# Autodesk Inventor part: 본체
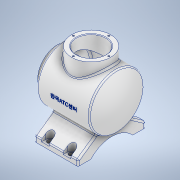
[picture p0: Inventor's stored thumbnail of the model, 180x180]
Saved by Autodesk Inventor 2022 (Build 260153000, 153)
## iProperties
Created: 2023-04
Part Number: 본체
Material: 알루미늄 6061
Document SubType Name: Modeling
Designer: Admin
Mass: 1296.7 g
Surface Area: 1060.45 cm^2
Volume: 480.258 cm^3
Density: 2.7 g/cm^3
Appearance: 알루미늄 - 평지
Author: Admin
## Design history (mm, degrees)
sketch "스케치1"
  geometry: L1 (-96.549, 0)-(166.291, 0) reference; L2 (0, -10.134)-(0, 60.805) reference; L3 (8.743, 0)-(128.743, 0); L4 (42.336, 50)-(-54, 50); L5 (-54, 50)-(-54, 43); L6 (-54, 0)-(54, 0); L7 (-54, 43)-(-54, 0); A1 r 113 centre (-59, 0) between (54, 0) and (42.336, 50); 3 further points
  constraints: 10 end point, 6 point on line, 2 perpendicular, 2 point on circle, 2 symmetric about line, 1 centre point, 1 collinear, 1 horizontal
  dimensions: "d2" = 113 radius of A1; "d4" = 108 distance from line of L6.end L5; "d75" = 100 diameter of L4 L1
revolve "회전1" sketch "스케치1" stored, may be unused: angle "d7" = 360 deg
sketch "스케치2"
  geometry: L1 (-77, -62)-(-77, 62); L2 (-134.515, 0)-(22.419, 0) reference; L3 (0, -110.456)-(0, 116.899) reference; L4 (-60, -77.977)-(-60, 84.42); L5 (-77, 62)-(-67, 62); L6 (-67, 62)-(-34.468, 15.54); L7 (-34.468, 15.54)-(-34.468, -15.54); L8 (-34.468, -15.54)-(-67, -62); L9 (-67, -62)-(-77, -62); A1 r 52.096 centre (-112.096, 0) between (-77, -38.5) and (-77, 38.5); 1 further point
  constraints: 14 end point, 4 symmetric about line, 2 point on circle, 2 point on line, 2 vertical, 1 centre point, 1 horizontal, 1 parallel, 1 perpendicular, 1 tangent
  dimensions: "d8" = 77 distance between parallel lines of L1 L3; "d9" = 124 distance of L1.start L1.end; "d11" = 77 distance of A1.end A1.start; "d12" = 17 distance between parallel lines of L1 L4; "d13" = 162.39677 distance of L4.start L4.end; "d14" = 55 deg angle of L6 L5; "d15" = 42.53177 distance between parallel lines of L1 L7; "d16" = 10 distance of L1.end L5.end
extrude "돌출1" join sketch "스케치2" distance "d17" = 34; taper "d18" = 0 deg; dims "d98" = 46, "d99" = 0
sketch "스케치12"
  geometry: L1 (38.5, -77)-(62, -77) reference; L2 (-86.8, 0)-(86.8, 0) reference; L3 (0, -102.4)-(0, 75.4) reference; C1 r 36 at (0, 0); 1 further point
  constraints: 1 centre point, 1 point on line
  dimensions: "d76" = 72 diameter of C1; "d77" = 77 distance from line of L1 C1.centre
extrude "돌출5" join sketch "스케치12" distance "d78" = 12; taper "d79" = 0 deg
node "작업 평면1"
sketch "스케치3"
  geometry: L1 (13, 23.5)-(13, 15.5); L2 (27, 23.5)-(27, 15.5); L3 (0, 23.5)-(80, 23.5) reference; L4 (0, 0)-(0, 23.5) reference; L5 (13, 23.5)-(27, 23.5); L6 (53, 23.5)-(53, 15.5); L7 (67, 23.5)-(67, 15.5); L8 (53, 23.5)-(67, 23.5); A1 r 7 centre (20, 15.5) between (13, 15.5) and (27, 15.5); A2 r 7 centre (60, 15.5) between (53, 15.5) and (67, 15.5); 1 further point
  constraints: 12 end point, 4 point on circle, 4 point on line, 4 tangent, 4 vertical, 2 centre point, 1 collinear, 1 perpendicular
  dimensions: "d20" = 14 distance between parallel lines of L2 L1; "d21" = 8 distance from line of L3 L1.end; "d22" = 20 distance from line of L4 A1.centre; "d23" = 14 distance between parallel lines of L7 L6; "d24" = 8 distance from line of L3 A2.centre; "d25" = 40 distance of A1.centre A2.centre
extrude "돌출2" cut sketch "스케치3" distance "d26" = 30; taper "d27" = 0 deg
node "작업 평면3"
sketch "스케치13"
  geometry: L1 (0, -102.4)-(0, 75.4) reference; L2 (-90, 0)-(78, 0) reference; L3 (-66, 36)-(-66, -36) reference; L4 (-66, 0)-(-47, 0); L5 (-47, 0)-(-47, 27); L6 (-47, 27)-(-66, 27); L7 (-66, 27)-(-66, 0); L8 (-47, 0)-(37.887, 0); L9 (37.887, 0)-(37.887, 43); L10 (37.887, 43)-(-47, 43); L11 (-47, 43)-(-47, 0); L12 (37.887, 0)-(47, 0); A1 r 113 centre (-59, 0) between (42.336, -50) and (42.336, 50) reference; A2 r 106 centre (-59, 0) between (47, 0) and (37.887, 43); 4 further points
  constraints: 18 end point, 4 parallel, 2 horizontal, 2 perpendicular, 2 point on circle, 1 centre point, 1 midpoint, 1 point on line
  dimensions: "d81" = 7 radial gap between concentric circles of A1 A2; "d82" = 54 diameter of L6 L2; "d83" = 86 diameter of L10 L2; "d84" = 19 distance of L5.end L6.end
revolve "회전3" sketch "스케치13" stored, may be unused: angle "d85" = 360 deg
sketch "스케치5"
  geometry: L1 (90, 0)-(-78, 0) reference; L2 (0, -86.8)-(0, 86.8) reference; L3 (66, -36)-(66, 36) reference; C1 r 36 at (4, 0); 1 further point
  constraints: 1 centre point, 1 point on line
  dimensions: "d35" = 72 diameter of C1; "d80" = 62 distance from line of L3 C1.centre
extrude "돌출3" join sketch "스케치5" stored distance "d37" = 30; taper "d38" = 0 deg
sketch "스케치6"
  geometry: C1 r 36 at (0, 0) reference; C2 r 27 at (0, 0); 1 further point
  constraints: 1 centre point, 1 coincident
  dimensions: "d39" = 54 diameter of C2
extrude "돌출4" cut sketch "스케치6" stored distance "d40" = 10; taper "d41" = 0 deg
sketch "스케치7"
  geometry: L1 (13, -23.5)-(13, -15.5) reference; L2 (27, -23.5)-(13, -23.5) reference; L3 (27, -15.5)-(27, -23.5) reference; L4 (53, -23.5)-(53, -15.5) reference; L5 (67, -23.5)-(53, -23.5) reference; L6 (67, -15.5)-(67, -23.5) reference; L7 (13, 100.5)-(13, 92.5) reference; L8 (27, 92.5)-(27, 100.5) reference; L9 (13, 100.5)-(27, 100.5) reference; L10 (53, 100.5)-(53, 92.5) reference; L11 (67, 92.5)-(67, 100.5) reference; L12 (53, 100.5)-(67, 100.5) reference; A1 r 7 centre (20, -15.5) between (27, -15.5) and (13, -15.5) reference; A2 r 7 centre (60, -15.5) between (67, -15.5) and (53, -15.5) reference; A3 r 7 centre (20, 92.5) between (13, 92.5) and (27, 92.5) reference; A4 r 7 centre (60, 92.5) between (53, 92.5) and (67, 92.5) reference; A5 r 7 centre (20, 92.5) between (13, 92.5) and (27, 92.5) reference; 5 further points
  constraints: 4 coincident
hole "구멍1" sketch "스케치7" at (20, 92.5), (60, 92.5), (20, -15.5), (60, -15.5) diameter "d42" = 9; stored, may be unused: countersink angle "d46" = 90 deg, drill point angle "d48" = 118 deg; dims "d43" = 6, "d44" = 4, "d45" = 2, "d47" = 8
sketch "스케치9" dims "d60" = 65
  geometry: L1 (0, 72.884)-(0, -78.398); C1 r 27 at (0, 0) reference; C2 r 36 at (0, 0) reference; 3 further points
  constraints: 2 end point, 2 point on line, 1 coincident, 1 vertical, 1 vertical alignment, 2 other
hole "구멍3" sketch "스케치9" at (0, 32.5) diameter "d61" = 3.242; stored, may be unused: countersink angle "d65" = 90 deg, drill point angle "d67" = 118 deg; dims "d62" = 8, "d63" = 4, "d64" = 2, "d66" = 10
node "작업 평면4"
sketch "스케치10"
  geometry: L1 (-90, 0)-(78, 0) reference; L2 (-66, 36)-(-66, -36) reference; 2 further points
  constraints: 1 point on line, 1 other
  dimensions: "d86" = 62 distance from line of L2 point (-4, 0)
feature "엠보싱1" sketch "스케치10" dims "d18" = 0, "d73" = 0.5, "d74" = 0
sketch "스케치14" dims "d87" = 65
  geometry: L1 (0, -102.4)-(0, 75.4) reference; C1 r 27 at (0, 0) reference; C2 r 36 at (0, 0) reference; 3 further points
  constraints: 1 coincident, 1 point on line, 1 vertical alignment, 2 other
hole "구멍4" sketch "스케치14" at (0, 32.5) diameter "d88" = 3.242; stored, may be unused: countersink angle "d92" = 90 deg, drill point angle "d94" = 118 deg; dims "d89" = 8, "d90" = 4, "d91" = 2, "d93" = 10
fillet "모깎기1" dims "d100" = 3
chamfer "모따기1" distance "d101" = 1; stored, may be unused: second distance "d102" = 2, angle "d103" = 45 deg
node "솔리드1"
mirror "미러1"
pattern_circular "원형 패턴2" dims angle "d69" = 360 deg
pattern_circular "원형 패턴3" dims angle "d96" = 360 deg
node "투영된 루프1"
node "투영된 루프2"
node "투영된 루프3"
node "투영된 루프4"
node "투영된 루프5"
node "투영된 루프7"
node "투영된 루프8"
feature "A9D066F2-1C7D-4E18-AEED-F7BC21143FA4" dims "d42" = 9, "d43" = 6, "d44" = 4, "d45" = 2, "d46" = 90 deg, "d47" = 8, "d48" = 118 deg
other parameters: "d19" = -6, "d34" = 65, "d71" = 153.75
